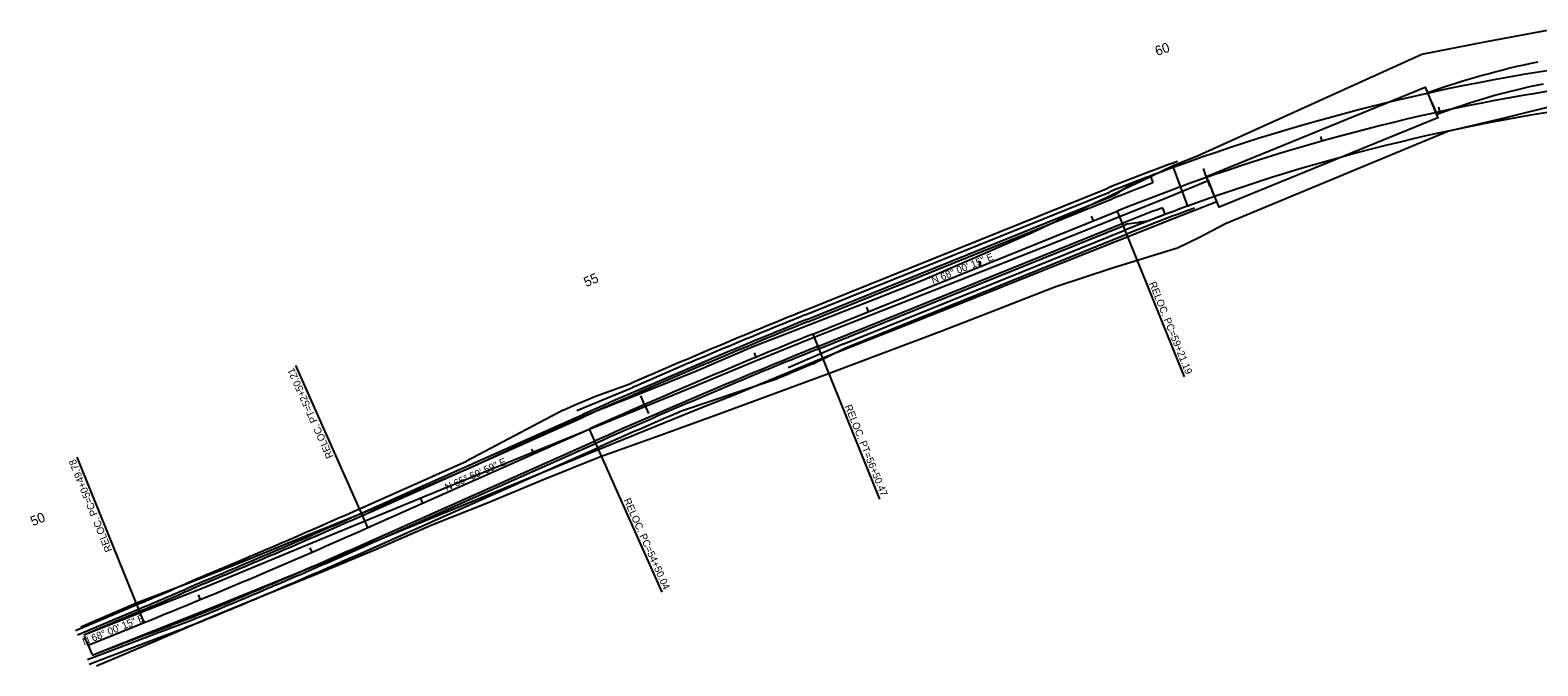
# Model space of a CAD drawing. Extents: x 1966723 to 1969285, y 1117431 to 1118041.
# Drawn here: x 1966723 to 1967966, y 1117431 to 1117955 of the extents above; entities that cross this region are included whole.
import ezdxf

# ---------------------------------------------------------------- set-up
doc = ezdxf.new("R2010")
doc.units = 0
for name, color, linetype in [('RD_EX_Bridge', 7, 'Continuous'), ('RD_EX_Road', 7, 'Continuous'), ('RD_EX_RW', 7, 'Continuous'), ('RD_HC_CL_Rel', 7, 'Continuous'), ('RD_HC_Data_Rel', 7, 'Continuous'), ('RD_HC_Data_Tic_Rel', 7, 'Continuous'), ('RD_HC_TX_Rel_Sta50', 7, 'Continuous'), ('RD_PD_Bridge', 7, 'Continuous'), ('RD_PD_EarthShd', 7, 'Continuous'), ('RD_PD_Final_TrvlWay', 7, 'Continuous'), ('RD_PD_PaveShd', 7, 'Continuous'), ('RD_Sketch3', 7, 'Continuous'), ('RD_Sketch4', 7, 'Continuous')]:
    doc.layers.add(name, color=color, linetype=linetype)

msp = doc.modelspace()

# ---------------------------------------------------------------- linework, layer by layer
at = {"layer": 'RD_EX_Bridge'}
msp.add_lwpolyline([(1967693.2, 1117834.7), (1967873.6, 1117908.4), (1967884, 1117883.1), (1967703.5, 1117809.4), (1967693.2, 1117834.7)], dxfattribs=at)
at = {"layer": 'RD_EX_Road'}
for points in [[(1967879, 1117895.5), (1967875.7, 1117903.5)], [(1967879, 1117895.5), (1967883.1, 1117885.6)], [(1966767.3, 1117456.6), (1966870.2, 1117497.3), (1966971.2, 1117539), (1967071.1, 1117580.2), (1967172.6, 1117621.5), (1967270.8, 1117661.7), (1967321.1, 1117682.6), (1967371.5, 1117702.9), (1967470.3, 1117741.6), (1967566.7, 1117779.5), (1967661.2, 1117817.5), (1967694.4, 1117831.2), (1967697.9, 1117822.8)], [(1967302.2, 1117654.1), (1967379.3, 1117686.2), (1967476.1, 1117724.4), (1967573.9, 1117763.5), (1967667.7, 1117800.7), (1967701.6, 1117814), (1967697.9, 1117822.8)], [(1966774.1, 1117439.9), (1966876.2, 1117480.4), (1966978.5, 1117522.1), (1967078.3, 1117563.1), (1967180.7, 1117605.1), (1967278, 1117644.7), (1967302.2, 1117654.1)]]:
    msp.add_lwpolyline(points, dxfattribs=at)
for centre, radius, start, end in [((1968104.9, 1117261.1), 682.1, 101.7162, 109.6396), ((1968080.6, 1117363), 558.7, 101.3479, 110.7006)]:
    msp.add_arc(centre, radius, start, end, dxfattribs=at)
at = {"layer": 'RD_EX_RW'}
for points in [[(1967870.6, 1117935.4), (1967922.7, 1117945.6), (1967974.5, 1117955.3)], [(1966764.8, 1117463.1), (1966810.5, 1117483.1), (1966857.3, 1117500.8), (1966903.7, 1117519.3), (1966950.1, 1117538.2), (1966996.4, 1117557), (1967042.7, 1117575.8), (1967088.6, 1117595.7), (1967134, 1117616.8), (1967179.6, 1117637.3), (1967226.1, 1117655.7), (1967272.5, 1117674.3), (1967318.5, 1117694.1), (1967365.1, 1117712.2), (1967411.6, 1117730.5), (1967458.2, 1117748.8), (1967504.1, 1117768.7), (1967549.8, 1117788.8), (1967595.2, 1117810), (1967640.5, 1117831.6), (1967646.9, 1117834.7), (1967665.2, 1117843.4), (1967686.2, 1117851.8), (1967870.6, 1117935.4)], [(1967663.6, 1117774.2), (1967669.1, 1117775.9), (1967686.8, 1117784.2), (1967708.8, 1117795.8), (1967892.1, 1117872), (1967938.9, 1117882.9), (1967985.3, 1117894.6)], [(1966777.6, 1117431), (1966823.7, 1117450.6), (1966869.6, 1117470.3), (1966915.9, 1117489.2), (1966962.2, 1117508), (1967008.4, 1117527.3), (1967054.2, 1117547.3), (1967100.7, 1117565.7), (1967146.8, 1117585), (1967193.3, 1117603.6), (1967240.4, 1117620.4), (1967287.4, 1117637.6), (1967381.3, 1117672.1), (1967428.1, 1117689.7), (1967474.9, 1117707.3), (1967521.5, 1117725.4), (1967568.1, 1117743.6), (1967615.7, 1117759.4), (1967663.6, 1117774.2)]]:
    msp.add_lwpolyline(points, dxfattribs=at)
at = {"layer": 'RD_HC_CL_Rel'}
for p, q in [((1967368.4, 1117704.6), (1967619.4, 1117806)), ((1967001.4, 1117545.1), (1967183.9, 1117626.3)), ((1966770.7, 1117448.1), (1966816.9, 1117466.8))]:
    msp.add_line(p, q, dxfattribs=at)
for centre, radius, start, end in [((1968232.6, 1116288.2), 1637, 87.7266, 111.9958), ((1969514.4, 1112392.1), 5729.6, 111.99584, 114.00015), ((1964670.9, 1122779.3), 5729.6, 291.9959, 294.00015)]:
    msp.add_arc(centre, radius, start, end, dxfattribs=at)
at = {"layer": 'RD_HC_Data_Rel'}
for p, q in [((1967619.4, 1117806), (1967674.6, 1117669.5)), ((1967368.4, 1117704.6), (1967423.4, 1117568.5)), ((1967001.4, 1117545.1), (1966941.9, 1117678.6)), ((1967183.9, 1117626.3), (1967243.9, 1117491.8)), ((1966816.9, 1117466.8), (1966761.8, 1117603.2))]:
    msp.add_line(p, q, dxfattribs=at)
at = {"layer": 'RD_HC_Data_Tic_Rel'}
for p, q in [((1967885.6, 1117888), (1967884.7, 1117891.9)), ((1967788.6, 1117863.8), (1967787.5, 1117867.7)), ((1967693.2, 1117833.8), (1967690.6, 1117841.3)), ((1967693.2, 1117833.8), (1967695.8, 1117826.2)), ((1967599.8, 1117798.1), (1967598.3, 1117801.8)), ((1967507.1, 1117760.7), (1967505.6, 1117764.4)), ((1967414.4, 1117723.2), (1967412.9, 1117726.9)), ((1967321.7, 1117685.5), (1967320.2, 1117689.2)), ((1967229.7, 1117646.5), (1967226.5, 1117653.8)), ((1967229.7, 1117646.5), (1967232.9, 1117639.1)), ((1967138.2, 1117606), (1967136.6, 1117609.6)), ((1967046.9, 1117565.3), (1967045.2, 1117569)), ((1966955.4, 1117524.8), (1966953.8, 1117528.5)), ((1966863.4, 1117485.8), (1966861.8, 1117489.5)), ((1966770.7, 1117448.1), (1966767.7, 1117455.5)), ((1966770.7, 1117448.1), (1966773.7, 1117440.7))]:
    msp.add_line(p, q, dxfattribs=at)
at = {"layer": 'RD_PD_Bridge'}
msp.add_line((1967665.7, 1117842), (1967677.4, 1117810.1), dxfattribs=at)
for radius in [1654, 1620]:
    msp.add_arc((1968232.6, 1116288.2), radius, 96.2174, 110.0424, dxfattribs=at)
at = {"layer": 'RD_PD_EarthShd'}
for p, q in [((1967360.8, 1117723.7), (1967611.8, 1117825.1)), ((1967395.3, 1117693.4), (1967627.1, 1117787)), ((1967368.3, 1117680.2), (1967395.3, 1117693.4)), ((1967368.3, 1117680.2), (1967350, 1117672.3)), ((1967190.1, 1117653.7), (1967218.4, 1117663.9)), ((1967336.1, 1117666.6), (1967260.1, 1117641.1)), ((1967162.5, 1117642), (1967082.7, 1117599.9)), ((1967162.5, 1117642), (1967171.6, 1117646)), ((1967171.6, 1117646), (1967190.1, 1117653.7)), ((1967008.3, 1117529.5), (1967190.9, 1117610.8)), ((1966994.5, 1117560.6), (1967082.7, 1117599.9)), ((1966760.4, 1117460.2), (1966810.8, 1117481.6)), ((1966771.5, 1117432.5), (1966822.7, 1117451.9))]:
    msp.add_line(p, q, dxfattribs=at)
for centre, radius, start, end in [((1968232.6, 1116288.2), 1657.5, 109.8696, 111.9958), ((1968232.6, 1116288.2), 1654, 110.7424, 111.9958), ((1968232.6, 1116288.2), 1616.5, 109.8652, 111.9958), ((1968232.6, 1116288.2), 1620, 110.7424, 111.9958), ((1969514.4, 1112392.1), 5750.1, 111.99584, 113.53467), ((1969514.4, 1112392.1), 5706.6, 112.2894, 112.4401), ((1969514.4, 1112392.1), 5712.6, 113.2426, 114.0002), ((1964670.9, 1122779.3), 5712.6, 292.497, 294.0002), ((1964670.9, 1122779.3), 5746.6, 292.49808, 294.00015), ((1966370.7, 1118566.3), 1170.6, 292.0836, 294.5329), ((1966245.3, 1119024.5), 1675.2, 290.1606, 291.8879)]:
    msp.add_arc(centre, radius, start, end, dxfattribs=at)
at = {"layer": 'RD_PD_Final_TrvlWay'}
for p, q in [((1967646.8, 1117835), (1967648.9, 1117829.4)), ((1967364.3, 1117714.8), (1967615.3, 1117816.2)), ((1967656.7, 1117808.8), (1967658.8, 1117803.2)), ((1967372.6, 1117694.4), (1967623.6, 1117795.8)), ((1966996.9, 1117555.1), (1967179.5, 1117636.4)), ((1967005.9, 1117535), (1967188.4, 1117616.3)), ((1966767.3, 1117456.6), (1966813.1, 1117476.1)), ((1966774.1, 1117439.9), (1966820.6, 1117457.6))]:
    msp.add_line(p, q, dxfattribs=at)
for centre, radius, start, end in [((1968232.6, 1116288.2), 1654, 110.0424, 110.7424), ((1968232.6, 1116288.2), 1648, 110.7424, 111.9958), ((1968232.6, 1116288.2), 1626, 110.7424, 111.9958), ((1968232.6, 1116288.2), 1620, 110.0424, 110.7424), ((1969514.4, 1112392.1), 5740.6, 111.99584, 114.00015), ((1969514.4, 1112392.1), 5718.6, 111.9958, 114.0002), ((1964670.9, 1122779.3), 5718.6, 292.4981, 294.0002), ((1964670.9, 1122779.3), 5740.6, 292.49808, 294.00015), ((1966370.7, 1118566.3), 1176.6, 292.0861, 294.5277), ((1966245.3, 1119024.5), 1669.2, 290.1606, 291.8879)]:
    msp.add_arc(centre, radius, start, end, dxfattribs=at)
at = {"layer": 'RD_PD_PaveShd'}
for p, q in [((1967363.6, 1117716.7), (1967614.6, 1117818.1)), ((1967373.3, 1117692.6), (1967624.3, 1117794)), ((1966996.1, 1117556.9), (1967178.7, 1117638.2)), ((1967006.7, 1117533.2), (1967189.2, 1117614.5)), ((1966761.9, 1117456.5), (1966812.3, 1117477.9)), ((1966770.1, 1117436.3), (1966821.3, 1117455.7))]:
    msp.add_line(p, q, dxfattribs=at)
for centre, radius, start, end in [((1968535.2, 1116489.9), 1615.3, 123.9652, 124.6097), ((1968232.6, 1116288.2), 1654, 110.7424, 111.262), ((1968232.6, 1116288.2), 1650, 111.8767, 111.9958), ((1968232.6, 1116288.2), 1624, 111.8767, 111.9958), ((1967867.6, 1116229.9), 1583.6, 98.0866, 98.7218), ((1968232.6, 1116288.2), 1620, 110.7424, 111.2729), ((1969514.4, 1112392.1), 5742.6, 111.99584, 114.00015), ((1969514.4, 1112392.1), 5716.6, 111.9958, 114.0002), ((1964670.9, 1122779.3), 5716.6, 292.4977, 294.0002), ((1964670.9, 1122779.3), 5742.6, 292.49798, 294.00015), ((1966370.7, 1118566.3), 1174.6, 292.0861, 294.5295), ((1966245.3, 1119024.5), 1671.2, 290.1606, 291.8883)]:
    msp.add_arc(centre, radius, start, end, dxfattribs=at)
at = {"layer": 'RD_Sketch3'}
for q in [(1967625.8, 1117790.3), (1967348.1, 1117676.9)]:
    msp.add_line((1967394, 1117696.6), q, dxfattribs=at)
msp.add_arc((1968232.6, 1116288.2), 1620, 109.8656, 111.9958, dxfattribs=at)
at = {"layer": 'RD_Sketch4'}
for p, q in [((1967362.1, 1117720.4), (1967613.1, 1117821.8)), ((1967173.7, 1117641.5), (1967219.8, 1117660.7))]:
    msp.add_line(p, q, dxfattribs=at)
for centre, radius, start, end in [((1968232.6, 1116288.2), 1654, 109.8692, 111.9958), ((1969514.4, 1112392.1), 5746.6, 111.99584, 113.53412)]:
    msp.add_arc(centre, radius, start, end, dxfattribs=at)

# ---------------------------------------------------------------- texts
at = {"layer": 'RD_HC_Data_Rel'}
for s, rotation, p in [('N 68%%d 00\' 15" E', 21.9958, (1967467.6, 1117745.8)), ('RELOC. PC=59+21.19', 291.9958, (1967645.6, 1117746.5)), ('RELOC. PT=52+50.21', 114.0002, (1966973.1, 1117603.6)), ('RELOC. PT=56+50.47', 291.9958, (1967394.6, 1117645.1)), ('RELOC. PC=50+49.78', 111.9959, (1966790.7, 1117526.3)), ('N 65%%d 59\' 59" E', 24.0002, (1967066.6, 1117575.2)), ('RELOC. PC=54+50.04', 294.0002, (1967212.2, 1117567.8)), ('N 68%%d 00\' 15" E', 21.9959, (1966767.4, 1117447.9))]:
    msp.add_text(s, height=6, rotation=rotation, dxfattribs=at).set_placement(p)
at = {"layer": 'RD_HC_TX_Rel_Sta50'}
for s, rotation, p in [('60', 19.2374, (1967652.3, 1117933.9)), ('55', 23.5006, (1967181.6, 1117743.3)), ('50', 21.9959, (1966725.1, 1117546.1))]:
    msp.add_text(s, height=8, rotation=rotation, dxfattribs=at).set_placement(p)

doc.saveas('drawing.dxf')
